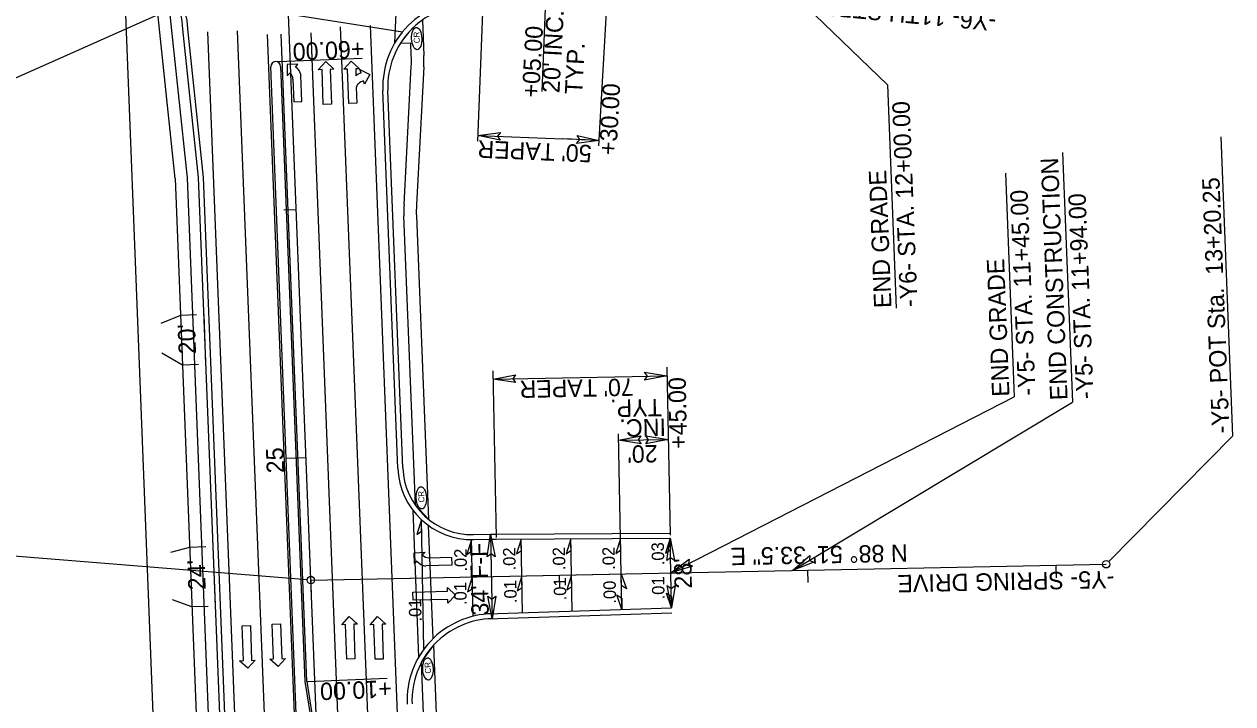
# Model space of a CAD drawing. Extents: x 1627861 to 1629601, y 761281 to 766239.
# Drawn here: x 1628338.3 to 1628824.9, y 762875.7 to 763149.5 of the extents above; entities that cross this region are included whole.
import ezdxf

# ---------------------------------------------------------------- set-up
doc = ezdxf.new("R2010")
doc.units = 0
for name, color, linetype in [('Cogo Default Point CELL', 7, 'Continuous'), ('Exist Other Culture Sign Leader', 7, 'Continuous'), ('Exist Property Tie Line Leader', 7, 'Continuous'), ('Exist Property Tie Line Text', 7, 'Continuous'), ('Exist Right of Way Line Leader', 7, 'Continuous'), ('Exist Right of Way Monument Leader', 7, 'Continuous'), ('Exist Right of Way Monument Text', 7, 'Continuous'), ('Exist Utilities Gas Meter CELL', 7, 'Continuous'), ('Exist Utilities Gas Meter Cogo Elevation', 7, 'Continuous'), ('Exist Utilities Gas Meter Cogo Number', 7, 'Continuous'), ('Exist Utilities Gas UG Line', 7, 'Continuous'), ('Exist Utilities Other Unknown UG SUE Text', 7, 'Continuous'), ('Exist Utilities Power UG Cable SUE LOS B Cogo Point CELL', 7, 'Continuous'), ('Exist Utilities Telephone UG Cable SUE LOS B Cogo Comment', 7, 'Continuous'), ('Exist Utilities Telephone UG Cable SUE LOS B Cogo Point CELL', 7, 'Continuous'), ('Exist Utilities Water Fire Hydrant Cogo Elevation', 7, 'Continuous'), ('Exist Utilities Water Fire Hydrant Cogo Number', 7, 'Continuous'), ('Exist Utilities Water Meter Cogo Elevation', 7, 'Continuous'), ('Exist Utilities Water UG Line SUE LOS B Cogo Number', 7, 'Continuous'), ('Exist Utilities Water Valve CELL', 7, 'Continuous'), ('Scratch_Level_0', 7, 'Continuous'), ('Scratch_Level_1', 7, 'Continuous'), ('Typical Terminator CELL', 7, 'Continuous')]:
    doc.layers.add(name, color=color, linetype=linetype)

msp = doc.modelspace()

# ---------------------------------------------------------------- linework, layer by layer
at = {"layer": 'Exist Other Culture Sign Leader'}
for p in [(1628756.4, 763097.81), (1628647.71, 762929.39)]:
    msp.add_line(p, (1628760.37, 762997.2), dxfattribs=at)
at = {"layer": 'Exist Property Tie Line Text'}
for p, q in [((1628447.87, 763074.69), (1628442.88, 763074.49)), ((1628753.69, 762931.5), (1628753.79, 762926.5)), ((1628553.73, 762927.52), (1628553.83, 762922.52)), ((1628653.71, 762929.51), (1628653.81, 762924.51))]:
    msp.add_line(p, q, dxfattribs=at)
at = {"layer": 'Exist Right of Way Line Leader'}
for p, q in [((1628442.93, 763175.97), (1628230.65, 763081.26)), ((1628824.95, 762983.71), (1628820.2, 763104.12)), ((1628774.99, 762932.97), (1628824.95, 762983.71)), ((1628452.26, 762925.69), (1628236.66, 762943.11))]:
    msp.add_line(p, q, dxfattribs=at)
for centre in [(1628773.94, 762931.9), (1628453.75, 762925.53)]:
    msp.add_circle(centre, 1.5, dxfattribs=at)
at = {"layer": 'Exist Right of Way Monument Leader'}
for p, q in [((1628456.77, 763131.12), (1628459.75, 763134.38)), ((1628459.75, 763134.38), (1628463.06, 763131.34)), ((1628467.01, 763131.3), (1628470.05, 763134.52)), ((1628470.05, 763134.52), (1628473.31, 763131.53)), ((1628448.57, 763133.31), (1628444.18, 763133.2)), ((1628444.18, 763133.2), (1628444.29, 763128.7)), ((1628444.29, 763128.7), (1628445.3, 763129.79)), ((1628447.56, 763132.22), (1628448.57, 763133.31)), ((1628458.27, 763131.17), (1628456.77, 763131.12)), ((1628458.77, 763117.18), (1628458.27, 763131.17)), ((1628463.06, 763131.34), (1628461.56, 763131.29)), ((1628461.56, 763131.29), (1628462.07, 763117.3)), ((1628468.51, 763131.36), (1628467.01, 763131.3)), ((1628469.01, 763117.57), (1628468.51, 763131.36)), ((1628473.31, 763131.53), (1628471.81, 763131.48)), ((1628471.81, 763131.48), (1628471.91, 763128.63)), ((1628473.97, 763129.8), (1628473.52, 763131.24)), ((1628473.52, 763131.24), (1628477.45, 763129.18)), ((1628446.54, 763127.33), (1628446.87, 763118.19)), ((1628450.16, 763118.3), (1628449.79, 763128.85)), ((1628475.38, 763125.25), (1628474.93, 763126.64)), ((1628477.45, 763129.18), (1628475.38, 763125.25)), ((1628472.07, 763124.13), (1628472.3, 763117.69)), ((1628446.87, 763118.19), (1628450.16, 763118.3)), ((1628462.07, 763117.3), (1628458.77, 763117.18)), ((1628472.3, 763117.69), (1628469.01, 763117.57)), ((1628495.29, 762936.54), (1628499.79, 762936.72)), ((1628495.46, 762932.15), (1628495.29, 762936.54)), ((1628499.79, 762936.72), (1628498.76, 762935.64)), ((1628496.48, 762933.22), (1628495.46, 762932.15)), ((1628510.53, 762931.51), (1628499.99, 762931.22)), ((1628501.29, 762934.56), (1628510.44, 762934.81)), ((1628510.44, 762934.81), (1628510.53, 762931.51)), ((1628494.83, 762920.71), (1628508.83, 762921.04)), ((1628494.91, 762917.42), (1628494.83, 762920.71)), ((1628508.83, 762921.04), (1628508.8, 762922.54)), ((1628508.8, 762922.54), (1628512.02, 762919.52)), ((1628508.91, 762917.75), (1628494.91, 762917.42)), ((1628508.94, 762916.25), (1628508.91, 762917.75)), ((1628512.02, 762919.52), (1628508.94, 762916.25)), ((1628466.21, 762907.57), (1628469.19, 762910.83)), ((1628469.19, 762910.83), (1628472.5, 762907.8)), ((1628477.64, 762907.55), (1628480.62, 762910.81)), ((1628480.62, 762910.81), (1628483.94, 762907.78)), ((1628426.1, 762907.07), (1628429.4, 762907.19)), ((1628426.6, 762893.08), (1628426.1, 762907.07)), ((1628429.4, 762907.19), (1628429.9, 762893.2)), ((1628438.25, 762907.74), (1628441.54, 762907.86)), ((1628438.75, 762893.75), (1628438.25, 762907.74)), ((1628441.54, 762907.86), (1628442.05, 762893.87)), ((1628467.7, 762907.63), (1628466.21, 762907.57)), ((1628468.21, 762893.64), (1628467.7, 762907.63)), ((1628472.5, 762907.8), (1628471, 762907.75)), ((1628471, 762907.75), (1628471.51, 762893.76)), ((1628479.14, 762907.61), (1628477.64, 762907.55)), ((1628479.64, 762893.62), (1628479.14, 762907.61)), ((1628483.94, 762907.78), (1628482.44, 762907.73)), ((1628482.44, 762907.73), (1628482.94, 762893.73)), ((1628425.1, 762893.03), (1628426.6, 762893.08)), ((1628428.41, 762890), (1628425.1, 762893.03)), ((1628431.4, 762893.26), (1628428.41, 762890)), ((1628429.9, 762893.2), (1628431.4, 762893.26)), ((1628437.25, 762893.7), (1628438.75, 762893.75)), ((1628440.56, 762890.66), (1628437.25, 762893.7)), ((1628443.54, 762893.92), (1628440.56, 762890.66)), ((1628442.05, 762893.87), (1628443.54, 762893.92)), ((1628471.51, 762893.76), (1628468.21, 762893.64)), ((1628482.94, 762893.73), (1628479.64, 762893.62))]:
    msp.add_line(p, q, dxfattribs=at)
for centre, radius, start, end in [((1628443.28, 763127.22), 3.28, 2.0586, 51.7168), ((1628444.64, 763127.87), 5.25, 10.7347, 56.0464), ((1628475.02, 763125.48), 4.43, 103.6494, 134.528), ((1628474.54, 763123.58), 2.52, 131.1317, 167.4437), ((1628475.99, 763122.33), 4.43, 103.7683, 134.6218), ((1628501.2, 762937.81), 3.28, 221.9037, 271.5619), ((1628500.64, 762936.41), 5.25, 217.5741, 262.8858)]:
    msp.add_arc(centre, radius, start, end, dxfattribs=at)
at = {"layer": 'Exist Right of Way Monument Text'}
for p, q in [((1628410.58, 763087.78), (1628404.22, 763147.58)), ((1628488.75, 762970.65), (1628482.75, 763122.82)), ((1628422.92, 762774.65), (1628410.58, 763087.78)), ((1628401.26, 763032.1), (1628393.36, 763028.91)), ((1628402.05, 763012.11), (1628393.83, 763016.99)), ((1628519.33, 762941.83), (1628526.18, 762941.97)), ((1628526.18, 762941.97), (1628528.44, 762942.02)), ((1628528.44, 762942.02), (1628598.45, 762942.44)), ((1628404.95, 762938.67), (1628397.27, 762936.58)), ((1628404.95, 762938.67), (1628404.95, 762938.67)), ((1628405.89, 762914.69), (1628398.02, 762917.54)), ((1628526.78, 762911.98), (1628529.04, 762912.02)), ((1628529.04, 762912.02), (1628599.01, 762914.3))]:
    msp.add_line(p, q, dxfattribs=at)
for centre, radius, start, end in [((1628369.24, 763146.2), 35, 2.2582, 92.2802), ((1628517.72, 763124.2), 35, 87.731, 182.2582), ((1628518.73, 762971.83), 30, 182.2582, 271.1407), ((1628527.47, 762876.98), 35, 91.1407, 182.2582)]:
    msp.add_arc(centre, radius, start, end, dxfattribs=at)
at = {"layer": 'Exist Utilities Gas Meter CELL'}
for p, q in [((1628486.22, 762102.11), (1628373.12, 764970.45)), ((1628453.75, 762925.53), (1628773.94, 762931.9)), ((1628453.75, 762925.53), (1628573.98, 762927.92))]:
    msp.add_line(p, q, dxfattribs=at)
at = {"layer": 'Exist Utilities Gas Meter Cogo Elevation'}
for p, q in [((1628408.58, 763087.7), (1628402.22, 763147.5)), ((1628490.75, 762970.71), (1628484.75, 763122.82)), ((1628420.93, 762774.57), (1628408.58, 763087.7)), ((1628519.29, 762943.83), (1628526.14, 762943.97))]:
    msp.add_line(p, q, dxfattribs=at)
for centre, radius, start, end in [((1628369.24, 763146.2), 33, 2.2582, 92.2802), ((1628517.72, 763124.2), 33, 87.731, 182.2582), ((1628518.73, 762971.83), 28, 182.2582, 271.1407), ((1628527.47, 762876.98), 33, 91.1407, 182.2582)]:
    msp.add_arc(centre, radius, start, end, dxfattribs=at)
at = {"layer": 'Exist Utilities Gas Meter Cogo Number'}
for points in [[(1628529.95, 763102.71), (1628521.02, 763104.61), (1628530.12, 763105.85), (1628528.91, 763104.3)], [(1628560.98, 763104.61), (1628569.88, 763102.56), (1628560.75, 763101.46), (1628561.99, 763103)], [(1628536.19, 763005.12), (1628527.16, 763006.49), (1628536.17, 763008.27), (1628535.05, 763006.64)], [(1628588.11, 763009.25), (1628597.14, 763007.88), (1628588.13, 763006.1), (1628589.24, 763007.72)], [(1628586.69, 762980.46), (1628577.66, 762981.84), (1628586.67, 762983.61), (1628585.56, 762981.99)], [(1628588.62, 762983.6), (1628597.65, 762982.23), (1628588.64, 762980.45), (1628589.75, 762982.08)], [(1628524.77, 762934.94), (1628526.14, 762943.97), (1628527.92, 762934.95), (1628526.3, 762936.07)], [(1628597.07, 762933.41), (1628598.45, 762942.44), (1628600.23, 762933.42), (1628598.6, 762934.54)], [(1628656.23, 762932.7), (1628647.71, 762929.39), (1628654.64, 762935.43), (1628654.48, 762933.46)], [(1628607.44, 762931.14), (1628598.72, 762928.41), (1628606.05, 762933.97), (1628605.75, 762932.02)], [(1628600.38, 762923.33), (1628599.01, 762914.3), (1628597.23, 762923.32), (1628598.85, 762922.2)], [(1628528.19, 762919.01), (1628526.82, 762909.98), (1628525.04, 762918.99), (1628526.66, 762917.88)]]:
    msp.add_lwpolyline(points, close=True, dxfattribs=at)
at = {"layer": 'Exist Utilities Gas UG Line'}
for p, q in [((1628516.57, 762163.69), (1628477.72, 763148.92)), ((1628451.12, 762161.11), (1628412.27, 763146.34)), ((1628463.11, 762161.58), (1628424.26, 763146.81)), ((1628451.93, 762749.59), (1628436.33, 763145.28)), ((1628452.11, 762884.71), (1628441.83, 763145.5)), ((1628464.1, 762885.18), (1628453.82, 763145.97)), ((1628504.58, 762163.21), (1628465.73, 763148.45)), ((1628452.11, 762884.71), (1628468.04, 762785.26)), ((1628468.04, 762785.26), (1628464.1, 762885.18))]:
    msp.add_line(p, q, dxfattribs=at)
at = {"layer": 'Exist Utilities Other Unknown UG SUE Text'}
for p, q in [((1628452.64, 762750.81), (1628437.59, 763132.33)), ((1628441.59, 763132.48), (1628451.36, 762884.68)), ((1628451.36, 762884.68), (1628467.29, 762785.23))]:
    msp.add_line(p, q, dxfattribs=at)
msp.add_arc((1628439.59, 763132.41), 2, 2.2582, 182.2582, dxfattribs=at)
at = {"layer": 'Exist Utilities Telephone UG Cable SUE LOS B Cogo Comment'}
for p, q in [((1628490.6, 763146.31), (1628401.24, 763160.39)), ((1628497.25, 762894.64), (1628494.93, 762953.56)), ((1628502.97, 762901.98), (1628501.17, 762947.5))]:
    msp.add_line(p, q, dxfattribs=at)
at = {"layer": 'Exist Utilities Telephone UG Cable SUE LOS B Cogo Point CELL'}
for p, q in [((1628526.14, 762943.97), (1628528.4, 762944.02)), ((1628528.43, 762944.02), (1628598.43, 762944.44)), ((1628529.1, 762910.02), (1628599.07, 762912.31)), ((1628526.82, 762909.98), (1628529.08, 762910.02))]:
    msp.add_line(p, q, dxfattribs=at)
at = {"layer": 'Exist Utilities Water Fire Hydrant Cogo Elevation'}
for centre in [(1628496.38, 763143.69), (1628498.24, 762958.67), (1628500.88, 762889.75)]:
    msp.add_ellipse(centre, major_axis=(-0.18, 4.48), ratio=0.462467, dxfattribs=at)
at = {"layer": 'Exist Utilities Water Fire Hydrant Cogo Number'}
msp.add_line((1628395.04, 762749.86), (1628378.53, 763173.02), dxfattribs=at)
at = {"layer": 'Exist Utilities Water Meter Cogo Elevation'}
for p, q in [((1628451.81, 762974.76), (1628443.82, 762974.45)), ((1628453.75, 762925.53), (1628453.91, 762917.53))]:
    msp.add_line(p, q, dxfattribs=at)
at = {"layer": 'Exist Utilities Water UG Line SUE LOS B Cogo Number'}
for p, q in [((1628489.79, 763200.42), (1628487.46, 763141.78)), ((1628499.31, 762897.77), (1628498.28, 762949.88)), ((1628519.06, 762910.96), (1628518.44, 762941.88)), ((1628539.03, 762912.35), (1628538.44, 762942.08)), ((1628559.02, 762913), (1628558.44, 762942.2)), ((1628579.01, 762913.65), (1628578.44, 762942.32)), ((1628599.01, 762914.3), (1628598.45, 762942.44))]:
    msp.add_line(p, q, dxfattribs=at)
at = {"layer": 'Exist Utilities Water Valve CELL'}
for p, q in [((1628390.08, 763171.79), (1628399.06, 763087.33)), ((1628404.07, 763087.53), (1628396.82, 763155.74)), ((1628498.66, 763151.13), (1628499.22, 763136.93)), ((1628494.02, 763141.85), (1628489.74, 763141.68)), ((1628494.21, 763136.96), (1628494.02, 763141.85)), ((1628491.28, 763076.79), (1628494.18, 763132.38)), ((1628499.19, 763132.35), (1628496.29, 763076.76)), ((1628399.09, 763087.33), (1628412.26, 762753.19)), ((1628417.03, 762759.18), (1628404.08, 763087.53)), ((1628495.85, 762955.69), (1628491.25, 763072.21)), ((1628496.26, 763072.18), (1628501.07, 762950.1)), ((1628501.07, 762950.1), (1628495.85, 762955.69)), ((1628498.34, 762892.48), (1628503.08, 762899.21)), ((1628503.08, 762899.21), (1628517.49, 762533.79)), ((1628512.26, 762539.39), (1628498.34, 762892.48))]:
    msp.add_line(p, q, dxfattribs=at)
for centre, radius, start, end in [((1628517.72, 763124.2), 33, 125.2948, 148.0029), ((1628444.25, 763134.99), 50, 357.012, 2.2582), ((1628449.26, 763134.96), 50, 357.012, 2.2582), ((1628541.21, 763074.18), 50, 177.012, 182.2582), ((1628546.22, 763074.15), 50, 177.012, 182.2582)]:
    msp.add_arc(centre, radius, start, end, dxfattribs=at)
at = {"layer": 'Scratch_Level_0'}
for p, q in [((1628643.48, 763166.09), (1628685.91, 763125.1)), ((1628548.2, 763159.16), (1628546.74, 763122.35)), ((1628569.76, 763100.47), (1628573.02, 763159.29)), ((1628520.93, 763102.29), (1628523.12, 763157.64)), ((1628440.73, 763134.45), (1628474.48, 763135.78)), ((1628685.91, 763125.1), (1628689.46, 763035.06)), ((1628521.02, 763104.61), (1628555.19, 763103.26)), ((1628733.41, 763089.4), (1628736.97, 762999.35)), ((1628411.54, 763012.49), (1628410.76, 763032.47)), ((1628527.09, 763009.86), (1628528.43, 762942.74)), ((1628527.16, 763006.49), (1628597.14, 763007.88)), ((1628597.07, 763011.3), (1628598.42, 762943.56)), ((1628598.72, 762928.41), (1628736.97, 762999.35)), ((1628578.44, 762942.32), (1628577.61, 762984.39)), ((1628577.66, 762981.84), (1628597.65, 762982.23)), ((1628526.14, 762943.97), (1628526.82, 762909.98)), ((1628599.01, 762914.3), (1628598.45, 762942.44)), ((1628415.39, 762915.06), (1628414.44, 762939.05)), ((1628452.56, 762884.72), (1628484.44, 762885.98))]:
    msp.add_line(p, q, dxfattribs=at)
msp.add_arc((1628518.35, 762173.43), 930.56, 86.82578, 87.73097, dxfattribs=at)
at = {"layer": 'Scratch_Level_1'}
for p, q in [((1628407.76, 763032.35), (1628401.26, 763032.1)), ((1628408.55, 763012.37), (1628402.05, 763012.11)), ((1628411.44, 762938.93), (1628404.95, 762938.67)), ((1628412.39, 762914.95), (1628405.89, 762914.69))]:
    msp.add_line(p, q, dxfattribs=at)
at = {"layer": 'Typical Terminator CELL'}
for points in [[(1628498.28, 762949.88), (1628496.4, 762943.84), (1628498.37, 762945.26)], [(1628518.44, 762941.88), (1628516.56, 762935.84), (1628518.53, 762937.25)], [(1628538.44, 762942.08), (1628536.56, 762936.04), (1628538.53, 762937.45)], [(1628558.44, 762942.2), (1628556.56, 762936.16), (1628558.53, 762937.57)], [(1628578.44, 762942.32), (1628576.56, 762936.28), (1628578.54, 762937.69)], [(1628598.45, 762942.44), (1628596.57, 762936.4), (1628598.54, 762937.81)], [(1628518.74, 762926.82), (1628516.86, 762920.78), (1628518.83, 762922.2)], [(1628538.74, 762927.22), (1628536.86, 762921.18), (1628538.83, 762922.59)], [(1628558.73, 762927.62), (1628556.85, 762921.58), (1628558.82, 762922.99)], [(1628578.73, 762928.01), (1628580.85, 762922.06), (1628578.82, 762923.39)], [(1628599.01, 762914.3), (1628596.89, 762920.26), (1628598.91, 762918.93)], [(1628579.01, 762913.65), (1628576.9, 762919.61), (1628578.92, 762918.28)]]:
    msp.add_lwpolyline(points, close=True, dxfattribs=at)

# ---------------------------------------------------------------- texts
at = {"layer": 'Cogo Default Point CELL'}
msp.add_text('N 88%%d 51\' 33.5" E', height=7, rotation=181.1407, dxfattribs=at).set_placement((1628693.97, 762939.92))
at = {"layer": 'Exist Other Culture Sign Leader'}
for s, rotation, p in [('-Y6- 11TH STREET', 174.6632, (1628729.92, 763153.57)), ('-Y6- STA. 12+00.00', 92.2582, (1628698.04, 763035.67)), ('END CONSTRUCTION', 92.2582, (1628758.43, 762998.14)), ('END GRADE', 92.2582, (1628687.55, 763035.26)), ('-Y5- STA. 11+45.00', 92.2582, (1628745.54, 762999.96)), ('-Y5- STA. 11+94.00', 92.2582, (1628768.92, 762998.55)), ('END GRADE', 92.2582, (1628735.05, 762999.55)), ('-Y5- SPRING DRIVE', 181.1407, (1628777.19, 762929.3))]:
    msp.add_text(s, height=7, rotation=rotation, dxfattribs=at).set_placement(p)
at = {"layer": 'Exist Property Tie Line Leader'}
msp.add_text('25', height=7, rotation=92.2582, dxfattribs=at).set_placement((1628443.04, 762968.71))
at = {"layer": 'Exist Right of Way Line Leader'}
msp.add_text('-Y5- POT Sta.  13+20.25', height=7, rotation=92.2582, dxfattribs=at).set_placement((1628823.61, 762984.71))
at = {"layer": 'Exist Utilities Power UG Cable SUE LOS B Cogo Point CELL'}
for s, rotation, p in [("20' INC.", 86.8258, (1628553.81, 763121.6)), ('+05.00', 86.8258, (1628545.66, 763119.76)), ('TYP.', 86.8258, (1628562.97, 763121.09)), ('+30.00', 86.8258, (1628576.74, 763096.61)), ("50' TAPER", 177.5939, (1628566.96, 763100.77)), ("70' TAPER", 181.1407, (1628583.7, 763006.79)), ('+45.00', 91.0255, (1628605.18, 762978.45)), ('TYP.', 181.1407, (1628595.01, 762998.56)), ('INC.', 181.1407, (1628596.66, 762990.59)), ("20'", 181.1407, (1628593.32, 762979.99)), ("34' F-F", 91.1407, (1628525.4, 762911.28)), ("28'", 91.1407, (1628607.19, 762922.19))]:
    msp.add_text(s, height=7, rotation=rotation, dxfattribs=at).set_placement(p)
at = {"layer": 'Exist Utilities Water Fire Hydrant Cogo Elevation'}
for p in [(1628497.64, 763141.85), (1628499.5, 762956.83), (1628502.13, 762887.91)]:
    msp.add_text('CR', height=2.4, rotation=92.2582, dxfattribs=at).set_placement(p)
at = {"layer": 'Exist Utilities Water UG Line SUE LOS B Cogo Number'}
for s, p in [('.03', (1628596.06, 762931.54)), ('.02', (1628516.63, 762928.97)), ('.02', (1628536.26, 762929.46)), ('.02', (1628556.26, 762929.58)), ('.02', (1628576.26, 762929.7)), ('.01', (1628536.68, 762916.29)), ('.01', (1628556.63, 762917.38)), ('.01', (1628596.18, 762917.78)), ('.01', (1628516.54, 762915.5)), ('.00', (1628576.66, 762916.06)), ('.01', (1628498.33, 762908.88))]:
    msp.add_text(s, height=5, rotation=91.1407, dxfattribs=at).set_placement(p)
at = {"layer": 'Scratch_Level_0'}
for s, rotation, p in [('+60.00', 182.2582, (1628475.18, 763142.98)), ("20'", 92.2582, (1628407.57, 763016.62)), ("24'", 92.2582, (1628411.46, 762921.59)), ('+10.00', 182.2582, (1628486.19, 762885.27))]:
    msp.add_text(s, height=7, rotation=rotation, dxfattribs=at).set_placement(p)

doc.saveas('drawing.dxf')
